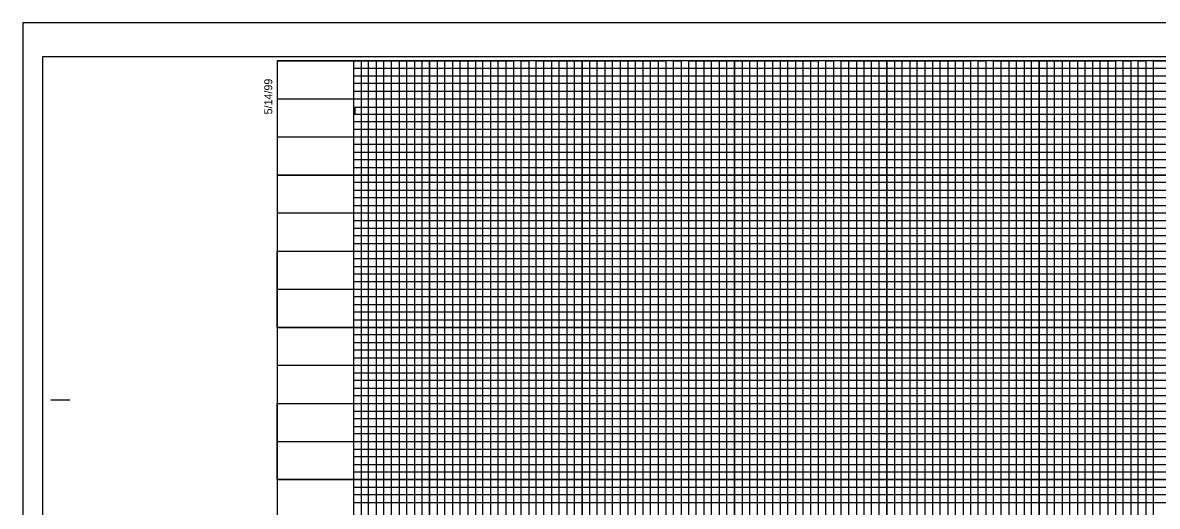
# Model space of a CAD drawing. Extents: x 553912 to 567693, y 512355 to 537539.
# Drawn here: x 566009 to 566754, y 514547 to 514865 of the extents above; entities that cross this region are included whole.
import ezdxf

# ---------------------------------------------------------------- set-up
doc = ezdxf.new("R2010")
doc.units = 0
for name, color, linetype in [('Default', 7, 'Continuous'), ('Old_Level_42', 7, 'Continuous'), ('Old_Level_51', 7, 'Continuous'), ('Old_Level_53', 7, 'Continuous'), ('Old_Level_54', 7, 'Continuous'), ('Prop ROW Permanent Easement CELL', 7, 'Continuous'), ('Sheet Row Area Data CELL', 7, 'Continuous'), ('Sheet Summary Guardrail CELL', 7, 'Continuous')]:
    doc.layers.add(name, color=color, linetype=linetype)

msp = doc.modelspace()

# ---------------------------------------------------------------- linework, layer by layer
at = {"layer": 'Default'}
msp.add_lwpolyline([(567693.42, 514864.71), (566009.42, 514864.71), (566009.42, 513764.71), (567693.42, 513764.71)], close=True, dxfattribs=at)
at = {"layer": 'Old_Level_42'}
for p, q in [((566226.42, 514839.71), (566226.42, 513814.71)), ((566276.42, 514839.71), (566276.42, 513814.71)), ((566326.42, 514839.71), (566326.42, 513814.71)), ((566376.42, 514839.71), (566376.42, 513814.71)), ((566426.42, 514839.71), (566426.42, 513814.71)), ((566476.42, 514839.71), (566476.42, 513814.71)), ((566526.42, 514839.71), (566526.42, 513814.71)), ((566576.42, 514839.71), (566576.42, 513814.71)), ((566626.42, 514839.71), (566626.42, 513814.71)), ((566676.42, 514839.71), (566676.42, 513814.71)), ((566726.42, 514839.71), (566726.42, 513814.71)), ((566176.42, 514814.71), (567476.37, 514814.71)), ((566176.42, 514764.71), (567476.37, 514764.71)), ((566176.42, 514714.71), (567476.37, 514714.71)), ((566176.42, 514664.71), (567676.42, 514664.71)), ((566176.42, 514614.71), (567676.42, 514614.71)), ((566176.42, 514564.71), (567676.42, 514564.71))]:
    msp.add_line(p, q, dxfattribs=at)
at = {"layer": 'Old_Level_51'}
msp.add_lwpolyline([(567688.92, 514842.26), (566022.42, 514842.26), (566022.42, 513787.16), (567688.92, 513787.16)], close=True, dxfattribs=at)
at = {"layer": 'Old_Level_53'}
msp.add_line((566027.92, 514617.21), (566040.42, 514617.21), dxfattribs=at)
msp.add_lwpolyline([(567676.42, 514839.71), (566176.42, 514839.71), (566176.42, 513789.71), (567676.42, 513789.71)], close=True, dxfattribs=at)
at = {"layer": 'Old_Level_54'}
for points in [[(566176.42, 514839.71), (566226.42, 514839.71), (566226.42, 513814.71), (566276.42, 513814.71), (566276.42, 514839.71), (566326.42, 514839.71), (566326.42, 513814.71), (566376.42, 513814.71), (566376.42, 514839.71), (566426.42, 514839.71), (566426.42, 513814.71), (566476.42, 513814.71), (566476.42, 514839.71), (566526.42, 514839.71), (566526.42, 513814.71), (566576.42, 513814.71), (566576.42, 514839.71), (566626.42, 514839.71), (566626.42, 513814.71), (566676.42, 513814.71), (566676.42, 514839.71), (566726.42, 514839.71), (566726.42, 513814.71), (566776.42, 513814.71)], [(567476.37, 514764.71), (566176.52, 514764.71), (566176.52, 514814.66), (567476.37, 514814.66)], [(567676.42, 514664.71), (566176.42, 514664.71), (566176.42, 514714.71), (567476.37, 514714.71)], [(567676.42, 514564.71), (566176.42, 514564.71), (566176.42, 514614.71), (567676.42, 514614.71)]]:
    msp.add_lwpolyline(points, dxfattribs=at)
at = {"layer": 'Prop ROW Permanent Easement CELL'}
for points in [[(566251.42, 513814.71), (566251.42, 514839.71), (566301.42, 514839.71), (566301.42, 513814.71), (566351.42, 513814.71), (566351.42, 514839.71), (566401.42, 514839.71), (566401.42, 513814.71), (566451.42, 513814.71), (566451.42, 514839.71), (566501.42, 514839.71), (566501.42, 513814.71), (566551.42, 513814.71), (566551.42, 514839.71), (566601.42, 514839.71), (566601.42, 513814.71), (566651.42, 513814.71), (566651.42, 514839.71), (566701.42, 514839.71), (566701.42, 513814.71), (566751.42, 513814.71), (566751.42, 514839.71), (566801.42, 514839.71)], [(566176.42, 514789.71), (567476.37, 514789.71)], [(567476.37, 514739.71), (566176.42, 514739.71), (566176.42, 514689.66), (567476.37, 514689.66)], [(567676.42, 514639.71), (566176.42, 514639.71), (566176.42, 514589.71), (567676.42, 514589.71)]]:
    msp.add_lwpolyline(points, dxfattribs=at)
at = {"layer": 'Sheet Row Area Data CELL'}
for p, q in [((567693.42, 514864.71), (566009.42, 514864.71)), ((566009.42, 514864.71), (566009.42, 513764.71))]:
    msp.add_line(p, q, dxfattribs=at)
at = {"layer": 'Sheet Summary Guardrail CELL'}
for p, q in [((567626.42, 514659.71), (566226.42, 514659.71)), ((566226.42, 514659.71), (566226.42, 514654.71)), ((566226.42, 514654.71), (567626.42, 514654.71)), ((567626.42, 514634.71), (566226.42, 514634.71))]:
    msp.add_line(p, q, dxfattribs=at)
for points in [[(566231.42, 514839.71), (566236.42, 514839.71), (566241.42, 514839.71), (566246.42, 514839.71), (566256.42, 514839.71), (566223.37, 514839.71), (566228.37, 514839.71), (566186.42, 514839.71), (566191.42, 514839.71), (566196.42, 514839.71), (566206.42, 514839.71), (566211.42, 514839.71), (566216.42, 514839.71), (566221.42, 514839.71), (566231.42, 514839.71), (566231.42, 513814.71)], [(566236.42, 513814.71), (566236.42, 514839.71), (566241.42, 514839.71), (566241.42, 513814.71)], [(566246.42, 513814.71), (566246.42, 514839.71), (566256.42, 514839.71), (566256.42, 513814.71)], [(566261.42, 513814.71), (566261.42, 514839.71), (566266.42, 514839.71), (566266.42, 513814.71)], [(566271.42, 513814.71), (566271.42, 514839.71), (566281.42, 514839.71), (566281.42, 513814.71)], [(566286.42, 513814.71), (566286.42, 514839.71), (566291.42, 514839.71), (566291.42, 513814.71)], [(566296.42, 513814.71), (566296.42, 514839.71), (566306.42, 514839.71), (566306.42, 513814.71)], [(566311.42, 513814.71), (566311.42, 514839.71), (566316.42, 514839.71), (566316.42, 513814.71)], [(566321.42, 513814.71), (566321.42, 514839.71), (566331.42, 514839.71), (566331.42, 513814.71)], [(566336.42, 513814.71), (566336.42, 514839.71), (566341.42, 514839.71), (566341.42, 513814.71)], [(566346.42, 513814.71), (566346.42, 514839.71), (566356.42, 514839.71), (566356.42, 513814.71)], [(566361.42, 513814.71), (566361.42, 514839.71), (566366.42, 514839.71), (566366.42, 513814.71)], [(566371.42, 513814.71), (566371.42, 514839.71), (566381.42, 514839.71), (566381.42, 513814.71)], [(566386.42, 513814.71), (566386.42, 514839.71), (566391.42, 514839.71), (566391.42, 513814.71)], [(566396.42, 513814.71), (566396.42, 514839.71), (566406.42, 514839.71), (566406.42, 513814.71)], [(566411.42, 513814.71), (566411.42, 514839.71), (566416.42, 514839.71), (566416.42, 513814.71)], [(566421.42, 513814.71), (566421.42, 514839.71), (566431.42, 514839.71), (566431.42, 513814.71)], [(566436.42, 513814.71), (566436.42, 514839.71), (566436.42, 514839.71), (566441.42, 514839.71), (566441.42, 513814.71)], [(566446.42, 513814.71), (566446.42, 514839.71), (566456.42, 514839.71), (566456.42, 513814.71)], [(566461.42, 513814.71), (566461.42, 514839.71), (566466.42, 514839.71), (566466.42, 513814.71)], [(566471.42, 513814.71), (566471.42, 514839.71), (566481.42, 514839.71), (566481.42, 513814.71)], [(566486.42, 513814.71), (566486.42, 514839.71), (566491.42, 514839.71), (566491.42, 513814.71)], [(566496.42, 513814.71), (566496.42, 514839.71), (566506.42, 514839.71), (566506.42, 513814.71)], [(566511.42, 513814.71), (566511.42, 514839.71), (566516.42, 514839.71), (566516.42, 513814.71)], [(566521.42, 513814.71), (566521.42, 514839.71), (566531.42, 514839.71), (566531.42, 513814.71)], [(566536.42, 513814.71), (566536.42, 514839.71), (566541.42, 514839.71), (566541.42, 513814.71)], [(566546.42, 513814.71), (566546.42, 514839.71), (566556.42, 514839.71), (566556.42, 513814.71)], [(566561.42, 514839.71), (566561.42, 513814.71), (566566.42, 513814.71), (566566.42, 514839.71)], [(566561.42, 514839.11), (566561.42, 513814.71), (566566.42, 513814.71), (566566.42, 514839.11)], [(566571.42, 513814.71), (566571.42, 514839.71), (566581.42, 514839.71), (566581.42, 513814.71)], [(566586.42, 513814.71), (566586.42, 514839.71), (566591.42, 514839.71), (566591.42, 513814.71)], [(566596.42, 513814.71), (566596.42, 514839.71), (566606.42, 514839.71), (566606.42, 513814.71)], [(566611.42, 513814.71), (566611.42, 514839.71), (566616.42, 514839.71), (566616.42, 513814.71)], [(566621.42, 513814.71), (566621.42, 514839.71), (566631.42, 514839.71), (566631.42, 513814.71)], [(566636.42, 513814.71), (566636.42, 514839.71), (566641.42, 514839.71), (566641.42, 513814.71)], [(566646.42, 513814.71), (566646.42, 514839.71), (566656.42, 514839.71), (566656.42, 513814.71)], [(566661.42, 513814.71), (566661.42, 514839.71), (566666.42, 514839.71), (566666.42, 513814.71)], [(566671.42, 513814.71), (566671.42, 514839.71), (566681.42, 514839.71), (566681.42, 513814.71)], [(566686.42, 513814.71), (566686.42, 514839.71), (566691.42, 514839.71), (566691.42, 513814.71)], [(566696.42, 513814.71), (566696.42, 514839.71), (566706.42, 514839.71), (566706.42, 513814.71)], [(566711.42, 514839.71), (566711.42, 513814.71), (566716.42, 513814.71), (566716.42, 514839.71), (566721.42, 514839.71), (566721.42, 513814.71), (566731.42, 513814.71), (566731.42, 514839.71), (566736.42, 514839.71), (566736.42, 513814.71), (566741.42, 513814.71), (566741.42, 514839.71), (566746.42, 514839.71), (566746.42, 513814.71)], [(567476.37, 514834.71), (566226.42, 514834.71), (566226.42, 514829.71), (567476.37, 514829.71)], [(567476.37, 514824.71), (566226.42, 514824.71), (566226.42, 514819.71), (567476.37, 514819.71)], [(567476.37, 514808.96), (566227.42, 514808.96), (566227.42, 514804.71), (567476.37, 514804.71)], [(567476.37, 514799.71), (566226.42, 514799.71), (566226.42, 514794.71), (567476.37, 514794.71)], [(567476.37, 514784.71), (566226.42, 514784.71), (566226.42, 514779.71), (567476.37, 514779.71)], [(567476.37, 514774.71), (566226.42, 514774.71), (566226.42, 514769.71), (567476.37, 514769.71)], [(567476.37, 514759.71), (566226.42, 514759.71), (566226.42, 514754.71), (567476.37, 514754.71)], [(567476.37, 514749.71), (566226.42, 514749.71), (566226.42, 514744.71), (567476.37, 514744.71)], [(567476.37, 514734.71), (566226.42, 514734.71), (566226.42, 514729.71), (567476.37, 514729.71)], [(567476.37, 514724.71), (566226.42, 514724.71), (566226.42, 514719.71), (567476.37, 514719.71)], [(567476.37, 514709.71), (566226.42, 514709.71), (566226.42, 514704.71), (567476.37, 514704.71)], [(567476.37, 514699.71), (566226.42, 514699.71), (566226.42, 514699.71), (566226.42, 514679.71), (567476.37, 514679.71)], [(566226.42, 514694.71), (567476.37, 514694.71)], [(567476.37, 514684.71), (566226.42, 514684.71)], [(567626.42, 514674.71), (566226.42, 514674.71), (566226.42, 514669.71), (567626.42, 514669.71)], [(567626.42, 514649.71), (566226.42, 514649.71), (566226.42, 514644.71), (567626.42, 514644.71)], [(567626.42, 514629.71), (566226.42, 514629.71), (566226.42, 514624.71), (567626.42, 514624.71)], [(567626.42, 514619.71), (566226.42, 514619.71)], [(566226.42, 514609.71), (567626.42, 514609.71)], [(567626.42, 514604.71), (566226.42, 514604.71), (566226.42, 514599.71), (567626.42, 514599.71)], [(567626.42, 514594.71), (566226.42, 514594.71), (566226.42, 514584.71), (567626.42, 514584.71)], [(567626.42, 514579.71), (566226.42, 514579.71), (566226.42, 514574.71), (567626.42, 514574.71)], [(567626.42, 514569.71), (566226.42, 514569.71), (566226.42, 514559.71), (567626.42, 514559.71)], [(567626.42, 514554.71), (566226.42, 514554.71), (566226.42, 514549.71), (567626.42, 514549.71)]]:
    msp.add_lwpolyline(points, dxfattribs=at)

# ---------------------------------------------------------------- texts
at = {"layer": 'Old_Level_53'}
msp.add_text('5/14/99', height=5.25, rotation=90, dxfattribs=at).set_placement((566173.17, 514804.51))

doc.saveas('drawing.dxf')
